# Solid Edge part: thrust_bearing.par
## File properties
Title: Thrust bearing
Author: Deepak Maini
Template: Normal.par
Last saved by: Robert a Rhodes jr
Revision: 8
Application: Solid Edge
Material: aluminum
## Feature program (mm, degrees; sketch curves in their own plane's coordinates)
sketch for "unnamed RevolvedProtrusion 1" plane through (0, 0, 0) normal (0, -1, 0) x-axis (1, 0, 0)
  line (47.625, 16.8036) -> (66.929, 16.8036)
  line (66.929, 16.8036) -> (73.025, 10.7076)
  line (73.025, 10.7076) -> (73.025, -12.0254)
  line (73.025, -12.0254) -> (66.929, -18.1214)
  line (66.929, -18.1214) -> (47.625, -18.1214)
  line (47.625, -18.1214) -> (47.625, -7.1994)
  line (61.5714, -7.1994) -> (47.625, -7.1994)
  line (61.5714, 5.8816) -> (61.5714, -7.1994)
  line (47.625, 5.8816) -> (61.5714, 5.8816)
  line (47.625, 5.8816) -> (47.625, 16.8036)
revolve "unnamed RevolvedProtrusion 1" add finite 360 deg
sketch for "unnamed RevolvedProtrusion 2" plane through (0, 0, 0) normal (1, 0, 0) x-axis (0, 1, 0)
  line (69.977, 13.7556) -> (73.0652, 13.7556)
  line (73.0652, 13.7556) -> (74.6125, 12.2083)
  line (74.6125, 12.2083) -> (74.6125, -13.4669)
  line (74.6125, -13.4669) -> (73.006, -15.0734)
  line (73.006, -15.0734) -> (69.977, -15.0734)
revolve "unnamed RevolvedProtrusion 2" add full turn 360 deg
sketch for "unnamed RevolvedProtrusion 3" plane through (0, 0, 0) normal (0, -1, 0) x-axis (1, 0, 0)
revolve "unnamed RevolvedProtrusion 3" add full turn 360 deg about sketch line (-54.9674, 10.1232) -> (-54.9674, -18.1214)
pattern "unnamed Pattern 1" of "unnamed RevolvedProtrusion 3"
pattern "unnamed Pattern 2"
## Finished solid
Body 1: solid body, 39 faces, 39 edges, 25 vertices.
  Faces by surface: torus 25, plane 6, cone 4, cylinder 4
  Edges by curve: circle 39
Bounding box of the edges (mm; curved faces can reach further): 149.225 x 149.225 x 34.925, from (-74.6125, -74.6125, -18.1214) to (74.6125, 74.6125, 16.8036).
Cylindrical faces by radius (mm): R47.625 x2, R61.5714 x1, R74.6125 x1
Conical faces (half-angle, radius in mm at the cone's reference point): 45 deg R66.929 x1, 45 deg R73.025 x1, 45 deg R73.0652 x1, 45 deg R74.6125 x1
Toroidal faces (ring radius, tube radius in mm): R-0.1023 r6.604 x25
Planar faces by outward normal: +z 3, -z 3
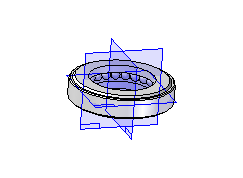
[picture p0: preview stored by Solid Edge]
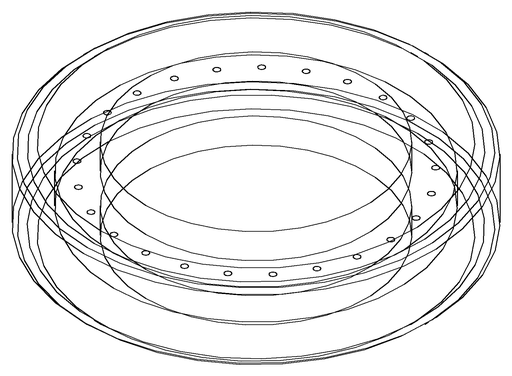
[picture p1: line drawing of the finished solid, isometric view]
